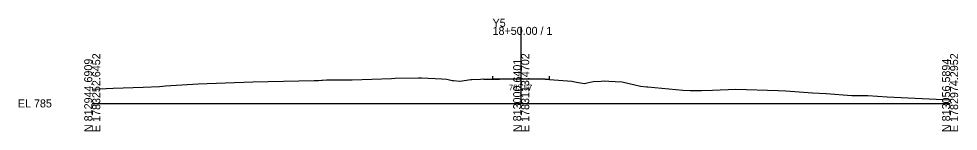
# Model space of a CAD drawing. Extents: x -26 to 1603, y -10 to 6526.
# Drawn here: x 1274.3 to 1602.8, y 5490.3 to 5529.5 of the extents above; entities that cross this region are included whole.
import ezdxf

# ---------------------------------------------------------------- set-up
doc = ezdxf.new("R2010")
doc.units = 0
for name, color, linetype in [('Exist Cross Section Cell', 7, 'Continuous'), ('Exist XS Center Line Elevation Label', 7, 'Continuous'), ('Exist XS Ground Line', 7, 'Continuous'), ('Prop XS EOT Tick Mark', 7, 'Continuous'), ('Prop XS Finish Grade Pavement', 7, 'Continuous')]:
    doc.layers.add(name, color=color, linetype=linetype)

msp = doc.modelspace()

# ---------------------------------------------------------------- linework, layer by layer
at = {"layer": 'Exist Cross Section Cell'}
for p, q in [((1450, 5500), (1450, 5526.72)), ((1300, 5500), (1450, 5500)), ((1450, 5500), (1600, 5500))]:
    msp.add_line(p, q, dxfattribs=at)
at = {"layer": 'Exist XS Ground Line'}
for p, q in [((1325.58, 5506.1), (1337.04, 5506.83)), ((1337.04, 5506.83), (1356.18, 5507.58)), ((1356.18, 5507.58), (1377.62, 5507.94)), ((1377.62, 5507.94), (1379.08, 5508.02)), ((1379.08, 5508.02), (1380.17, 5508.11)), ((1380.17, 5508.11), (1380.51, 5508.16)), ((1380.51, 5508.16), (1381.88, 5508.24)), ((1381.88, 5508.24), (1383.09, 5508.22)), ((1383.09, 5508.22), (1385.67, 5508.18)), ((1385.67, 5508.18), (1386.89, 5508.2)), ((1386.89, 5508.2), (1389.81, 5508.2)), ((1389.81, 5508.2), (1390.93, 5508.19)), ((1390.93, 5508.19), (1404.6, 5508.72)), ((1404.6, 5508.72), (1405.92, 5508.77)), ((1405.92, 5508.77), (1414.08, 5508.89)), ((1414.08, 5508.89), (1414.47, 5508.91)), ((1414.47, 5508.91), (1415.18, 5508.87)), ((1415.18, 5508.87), (1422.22, 5508.55)), ((1422.22, 5508.55), (1424.06, 5508.41)), ((1424.06, 5508.41), (1425.85, 5508.02)), ((1425.85, 5508.02), (1426.36, 5507.96)), ((1426.36, 5507.96), (1428.5, 5507.76)), ((1428.5, 5507.76), (1432.38, 5508.29)), ((1432.38, 5508.29), (1432.74, 5508.37)), ((1432.74, 5508.37), (1435.8, 5508.51)), ((1435.8, 5508.51), (1436.6, 5508.53)), ((1436.6, 5508.53), (1436.99, 5508.5)), ((1436.99, 5508.5), (1440.1, 5508.41)), ((1440.1, 5508.41), (1442.46, 5508.44)), ((1442.46, 5508.44), (1450, 5508.57)), ((1450, 5508.57), (1450.44, 5508.56)), ((1450.44, 5508.56), (1458.36, 5508.42)), ((1458.36, 5508.42), (1459.87, 5508.39)), ((1459.87, 5508.39), (1467.72, 5507.78)), ((1467.72, 5507.78), (1469.39, 5507.45)), ((1469.39, 5507.45), (1472.09, 5506.95)), ((1472.09, 5506.95), (1473.11, 5507.2)), ((1473.11, 5507.2), (1475.19, 5507.68)), ((1475.19, 5507.68), (1478, 5507.79)), ((1478, 5507.79), (1478.99, 5507.83)), ((1478.99, 5507.83), (1480.63, 5507.75)), ((1480.63, 5507.75), (1482.87, 5507.67)), ((1482.87, 5507.67), (1485.34, 5507.53)), ((1485.34, 5507.53), (1489.7, 5506.47)), ((1489.7, 5506.47), (1491.77, 5505.99)), ((1300, 5504.92), (1307.3, 5505.28)), ((1307.3, 5505.28), (1317.79, 5505.67)), ((1317.79, 5505.67), (1323.52, 5505.93)), ((1323.52, 5505.93), (1325.58, 5506.1)), ((1491.77, 5505.99), (1493.97, 5505.84)), ((1493.97, 5505.84), (1494.33, 5505.83)), ((1494.33, 5505.83), (1506.5, 5504.62)), ((1506.5, 5504.62), (1509.05, 5504.52)), ((1509.05, 5504.52), (1513.03, 5504.54)), ((1513.03, 5504.54), (1516.96, 5504.66)), ((1516.96, 5504.66), (1525.06, 5504.99)), ((1525.06, 5504.99), (1539.93, 5504.51)), ((1539.93, 5504.51), (1542.54, 5504.4)), ((1542.54, 5504.4), (1551.87, 5503.74)), ((1551.87, 5503.74), (1556.69, 5503.43)), ((1556.69, 5503.43), (1565.69, 5502.8)), ((1565.69, 5502.8), (1571.2, 5502.8)), ((1571.2, 5502.8), (1578.01, 5502.29)), ((1578.01, 5502.29), (1600, 5501.21))]:
    msp.add_line(p, q, dxfattribs=at)
at = {"layer": 'Prop XS EOT Tick Mark'}
for p, q in [((1440.1, 5508.54), (1440.1, 5509.54)), ((1459.87, 5508.51), (1459.87, 5509.51))]:
    msp.add_line(p, q, dxfattribs=at)
at = {"layer": 'Prop XS Finish Grade Pavement'}
for p, q in [((1440.1, 5508.54), (1442.45, 5508.57)), ((1442.45, 5508.57), (1450, 5508.7)), ((1450, 5508.7), (1450.44, 5508.69)), ((1450.44, 5508.69), (1458.36, 5508.54)), ((1458.36, 5508.54), (1459.87, 5508.51))]:
    msp.add_line(p, q, dxfattribs=at)

# ---------------------------------------------------------------- texts
at = {"layer": 'Exist Cross Section Cell'}
for s, p in [('Y5', (1440, 5526.72)), ('18+50.00 / 1', (1440, 5523.92)), ('EL 785', (1274, 5498.6))]:
    msp.add_text(s, height=2.8, dxfattribs=at).set_placement(p)
for s, p in [('E 1783252.6452', (1302.8, 5490)), ('E 1783113.4702', (1452.8, 5490)), ('E 1782974.2952', (1602.8, 5490)), ('N 812944.6909', (1300, 5490)), ('N 813000.6401', (1450, 5490)), ('N 813056.5894', (1600, 5490))]:
    msp.add_text(s, height=2.8, rotation=90, dxfattribs=at).set_placement(p)
at = {"layer": 'Exist XS Center Line Elevation Label'}
msp.add_text('793.57', height=2, dxfattribs=at).set_placement((1445.7, 5504.57))

doc.saveas('drawing.dxf')
